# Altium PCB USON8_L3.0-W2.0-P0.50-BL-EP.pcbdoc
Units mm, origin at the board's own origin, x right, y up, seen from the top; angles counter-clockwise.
Board outline 14.99 x 16.35 mm, 2 copper layers (Top Layer, Bottom Layer), stack 0 mm thick; 1 components, 0 nets, 9 pads, 0 vias.
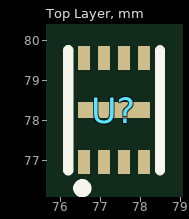
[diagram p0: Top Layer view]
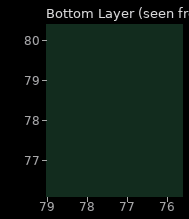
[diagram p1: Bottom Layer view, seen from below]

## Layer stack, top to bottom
Top Layer: signal copper (thickness not stored)
Bottom Layer: signal copper (thickness not stored)

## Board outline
84.841,69.85 69.85,69.85 69.85,86.2 84.841,86.2

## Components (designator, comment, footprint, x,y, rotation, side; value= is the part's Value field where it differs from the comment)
U? "" USON8_L3.0-W2.0-P0.50-BL-EP 77.34,78.25 r0 top

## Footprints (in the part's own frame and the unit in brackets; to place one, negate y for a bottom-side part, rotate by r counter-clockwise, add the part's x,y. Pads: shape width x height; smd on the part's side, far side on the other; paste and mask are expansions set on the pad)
USON8_L3.0-W2.0-P0.50-BL-EP [mm]
  rect 0.3x0.6 smd: 1(-0.75,-1.3) 2(-0.25,-1.3) 3(0.25,-1.3) 4(0.75,-1.3) 5(0.75,1.3) 6(0.25,1.3) 7(-0.25,1.3) 8(-0.75,1.3)
  rect 1.8x0.4 smd: 9(0,0)
  silkscreen extent -1.14,-2.05 1.15,1.5

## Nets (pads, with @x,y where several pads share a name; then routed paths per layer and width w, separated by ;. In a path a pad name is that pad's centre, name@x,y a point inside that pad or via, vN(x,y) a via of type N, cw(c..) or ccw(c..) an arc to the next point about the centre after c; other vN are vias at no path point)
pads on no net: U?.1 U?.2 U?.3 U?.4 U?.5 U?.6 U?.7 U?.8 U?.9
